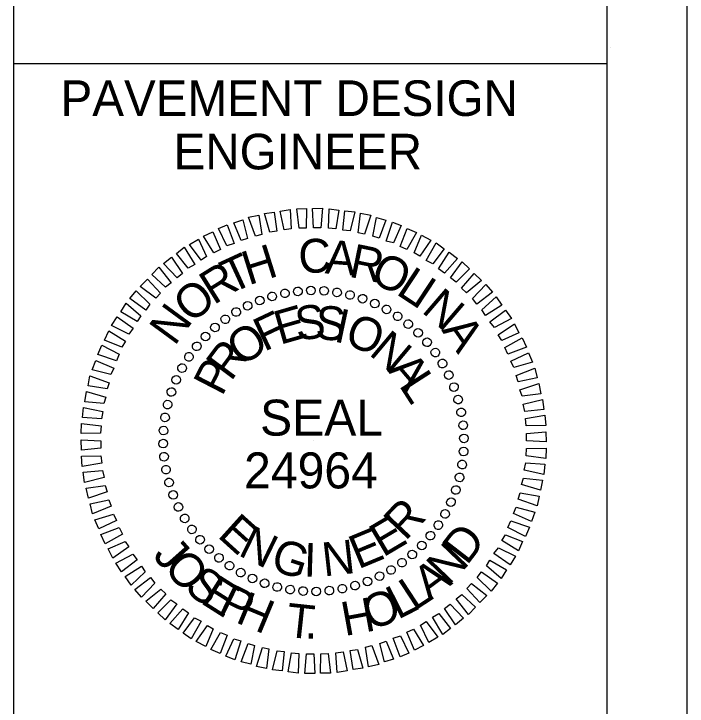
# Model space of a CAD drawing. Extents: x 1553884 to 1554215, y 810431 to 810779.
# Drawn here: x 1554139.32 to 1554156.35, y 810553.55 to 810571.05 of the extents above; entities that cross this region are included whole.
import ezdxf

# ---------------------------------------------------------------- set-up
doc = ezdxf.new("R2010")
doc.units = 0
for name, color, linetype in [('Exist Structure Minor Drop Inlet Top Elevation', 7, 'Continuous'), ('Old_Level_2', 7, 'Continuous'), ('Prop Lane Arrow CELL', 7, 'Continuous'), ('Typical Arrow Superelevation CELL', 7, 'Continuous')]:
    doc.layers.add(name, color=color, linetype=linetype)

msp = doc.modelspace()

# ---------------------------------------------------------------- linework, layer by layer
at = {"layer": 'Exist Structure Minor Drop Inlet Top Elevation'}
for p, q in [((1554154.423, 810570.205), (1554154.423, 810570.205)), ((1554146.178, 810563.991), (1554146.178, 810563.991)), ((1554146.503, 810564.042), (1554146.503, 810564.042)), ((1554146.837, 810564.063), (1554146.837, 810564.063)), ((1554147.171, 810564.054), (1554147.171, 810564.054)), ((1554147.497, 810564.014), (1554147.497, 810564.014)), ((1554145.537, 810563.813), (1554145.537, 810563.813)), ((1554145.853, 810563.917), (1554145.853, 810563.917)), ((1554147.824, 810563.952), (1554147.824, 810563.952)), ((1554148.144, 810563.859), (1554148.144, 810563.859)), ((1554145.236, 810563.679), (1554145.236, 810563.679)), ((1554148.45, 810563.735), (1554148.45, 810563.735)), ((1554144.943, 810563.522), (1554144.943, 810563.522)), ((1554148.748, 810563.589), (1554148.748, 810563.589)), ((1554144.665, 810563.335), (1554144.665, 810563.335)), ((1554149.032, 810563.411), (1554149.032, 810563.411)), ((1554144.403, 810563.134), (1554144.403, 810563.134)), ((1554149.301, 810563.219), (1554149.301, 810563.219)), ((1554149.547, 810562.996), (1554149.547, 810562.996)), ((1554144.165, 810562.902), (1554144.165, 810562.902)), ((1554149.779, 810562.757), (1554149.779, 810562.757)), ((1554143.942, 810562.655), (1554143.942, 810562.655)), ((1554149.981, 810562.495), (1554149.981, 810562.495)), ((1554143.749, 810562.386), (1554143.749, 810562.386)), ((1554150.168, 810562.218), (1554150.168, 810562.218)), ((1554143.572, 810562.103), (1554143.572, 810562.103)), ((1554150.324, 810561.925), (1554150.324, 810561.925)), ((1554143.426, 810561.805), (1554143.426, 810561.805)), ((1554150.459, 810561.624), (1554150.459, 810561.624)), ((1554143.302, 810561.499), (1554143.302, 810561.499)), ((1554143.209, 810561.179), (1554143.209, 810561.179)), ((1554150.563, 810561.307), (1554150.563, 810561.307)), ((1554143.146, 810560.852), (1554143.146, 810560.852)), ((1554150.637, 810560.982), (1554150.637, 810560.982)), ((1554150.688, 810560.657), (1554150.688, 810560.657)), ((1554143.107, 810560.525), (1554143.107, 810560.525)), ((1554150.709, 810560.324), (1554150.709, 810560.324)), ((1554143.097, 810560.191), (1554143.097, 810560.191)), ((1554146.903, 810560.258), (1554146.903, 810560.258)), ((1554150.699, 810559.99), (1554150.699, 810559.99)), ((1554143.118, 810559.858), (1554143.118, 810559.858)), ((1554150.66, 810559.663), (1554150.66, 810559.663)), ((1554143.17, 810559.533), (1554143.17, 810559.533)), ((1554150.597, 810559.336), (1554150.597, 810559.336)), ((1554143.243, 810559.208), (1554143.243, 810559.208)), ((1554143.348, 810558.891), (1554143.348, 810558.891)), ((1554150.504, 810559.016), (1554150.504, 810559.016)), ((1554143.482, 810558.59), (1554143.482, 810558.59)), ((1554150.38, 810558.711), (1554150.38, 810558.711)), ((1554150.234, 810558.412), (1554150.234, 810558.412)), ((1554143.639, 810558.297), (1554143.639, 810558.297)), ((1554143.825, 810558.02), (1554143.825, 810558.02)), ((1554150.057, 810558.129), (1554150.057, 810558.129)), ((1554149.865, 810557.86), (1554149.865, 810557.86)), ((1554144.027, 810557.758), (1554144.027, 810557.758)), ((1554144.259, 810557.519), (1554144.259, 810557.519)), ((1554149.641, 810557.613), (1554149.641, 810557.613)), ((1554149.403, 810557.382), (1554149.403, 810557.382)), ((1554144.505, 810557.296), (1554144.505, 810557.296)), ((1554149.141, 810557.18), (1554149.141, 810557.18)), ((1554144.774, 810557.104), (1554144.774, 810557.104)), ((1554148.864, 810556.993), (1554148.864, 810556.993)), ((1554145.058, 810556.927), (1554145.058, 810556.927)), ((1554148.571, 810556.836), (1554148.571, 810556.836)), ((1554145.356, 810556.78), (1554145.356, 810556.78)), ((1554145.662, 810556.656), (1554145.662, 810556.656)), ((1554148.269, 810556.702), (1554148.269, 810556.702)), ((1554145.982, 810556.563), (1554145.982, 810556.563)), ((1554146.309, 810556.501), (1554146.309, 810556.501)), ((1554146.636, 810556.461), (1554146.636, 810556.461)), ((1554146.969, 810556.452), (1554146.969, 810556.452)), ((1554147.303, 810556.473), (1554147.303, 810556.473)), ((1554147.628, 810556.524), (1554147.628, 810556.524)), ((1554147.953, 810556.598), (1554147.953, 810556.598))]:
    msp.add_line(p, q, dxfattribs=at)
for points in [[(1554146.158, 810565.591), (1554146.058, 810566.067), (1554146.308, 810566.109), (1554146.339, 810565.617)], [(1554146.536, 810565.635), (1554146.475, 810566.127), (1554146.725, 810566.132), (1554146.718, 810565.638)], [(1554146.9, 810565.642), (1554146.876, 810566.134), (1554147.126, 810566.138), (1554147.082, 810565.645)], [(1554147.279, 810565.633), (1554147.293, 810566.126), (1554147.544, 810566.093), (1554147.462, 810565.614)], [(1554147.644, 810565.587), (1554147.696, 810566.073), (1554147.947, 810566.047), (1554147.827, 810565.567)], [(1554145.432, 810565.434), (1554145.257, 810565.909), (1554145.514, 810565.966), (1554145.591, 810565.475)], [(1554145.795, 810565.531), (1554145.658, 810566.007), (1554145.907, 810566.042), (1554145.976, 810565.557)], [(1554148.032, 810565.517), (1554148.092, 810566.011), (1554148.351, 810565.963), (1554148.192, 810565.482)], [(1554148.398, 810565.433), (1554148.496, 810565.905), (1554148.732, 810565.841), (1554148.558, 810565.382)], [(1554144.709, 810565.186), (1554144.496, 810565.623), (1554144.715, 810565.717), (1554144.89, 810565.243)], [(1554145.07, 810565.322), (1554144.881, 810565.773), (1554145.114, 810565.846), (1554145.229, 810565.377)], [(1554148.741, 810565.31), (1554148.899, 810565.79), (1554149.121, 810565.703), (1554148.924, 810565.26)], [(1554144.378, 810565.014), (1554144.121, 810565.434), (1554144.354, 810565.544), (1554144.544, 810565.092)], [(1554149.092, 810565.172), (1554149.266, 810565.63), (1554149.503, 810565.528), (1554149.26, 810565.099)], [(1554149.444, 810565.011), (1554149.633, 810565.454), (1554149.871, 810565.329), (1554149.59, 810564.923)], [(1554144.055, 810564.826), (1554143.76, 810565.223), (1554143.993, 810565.356), (1554144.198, 810564.92)], [(1554149.751, 810564.819), (1554150.001, 810565.264), (1554150.201, 810565.115), (1554149.919, 810564.731)], [(1554143.733, 810564.623), (1554143.438, 810564.997), (1554143.633, 810565.152), (1554143.898, 810564.717)], [(1554150.065, 810564.605), (1554150.331, 810565.027), (1554150.538, 810564.871), (1554150.211, 810564.501)], [(1554143.449, 810564.383), (1554143.109, 810564.741), (1554143.311, 810564.904), (1554143.591, 810564.492)], [(1554150.365, 810564.375), (1554150.661, 810564.782), (1554150.846, 810564.603), (1554150.511, 810564.272)], [(1554143.157, 810564.143), (1554142.81, 810564.463), (1554142.989, 810564.648), (1554143.299, 810564.252)], [(1554150.643, 810564.122), (1554150.962, 810564.492), (1554151.147, 810564.313), (1554150.766, 810564.003)], [(1554142.912, 810563.866), (1554142.52, 810564.162), (1554142.699, 810564.348), (1554143.031, 810563.989)], [(1554150.92, 810563.854), (1554151.255, 810564.209), (1554151.425, 810564.014), (1554151.029, 810563.712)], [(1554142.659, 810563.566), (1554142.252, 810563.854), (1554142.416, 810564.054), (1554142.763, 810563.712)], [(1554151.16, 810563.57), (1554151.518, 810563.902), (1554151.666, 810563.685), (1554151.254, 810563.427)], [(1554142.444, 810563.274), (1554142.023, 810563.517), (1554142.163, 810563.739), (1554142.533, 810563.419)], [(1554151.363, 810563.263), (1554151.759, 810563.565), (1554151.907, 810563.348), (1554151.479, 810563.121)], [(1554142.23, 810562.959), (1554141.794, 810563.171), (1554141.934, 810563.394), (1554142.341, 810563.105)], [(1554151.573, 810562.94), (1554151.985, 810563.22), (1554152.095, 810562.987), (1554151.667, 810562.798)], [(1554142.054, 810562.63), (1554141.618, 810562.804), (1554141.72, 810563.041), (1554142.142, 810562.776)], [(1554151.738, 810562.617), (1554152.174, 810562.86), (1554152.284, 810562.626), (1554151.817, 810562.452)], [(1554141.916, 810562.279), (1554141.443, 810562.437), (1554141.545, 810562.674), (1554141.989, 810562.447)], [(1554151.888, 810562.271), (1554152.339, 810562.483), (1554152.435, 810562.25), (1554151.967, 810562.113)], [(1554141.778, 810561.935), (1554141.305, 810562.056), (1554141.392, 810562.292), (1554141.851, 810562.096)], [(1554152.023, 810561.909), (1554152.498, 810562.099), (1554152.555, 810561.85), (1554152.079, 810561.751)], [(1554141.678, 810561.569), (1554141.199, 810561.652), (1554141.247, 810561.903), (1554141.728, 810561.729)], [(1554152.121, 810561.547), (1554152.596, 810561.707), (1554152.653, 810561.45), (1554152.176, 810561.389)], [(1554141.593, 810561.204), (1554141.115, 810561.248), (1554141.163, 810561.507), (1554141.644, 810561.364)], [(1554152.203, 810561.184), (1554152.694, 810561.307), (1554152.728, 810561.049), (1554152.244, 810561.003)], [(1554141.539, 810560.816), (1554141.054, 810560.846), (1554141.079, 810561.104), (1554141.574, 810560.999)], [(1554152.262, 810560.821), (1554152.754, 810560.906), (1554152.773, 810560.648), (1554152.281, 810560.64)], [(1554141.515, 810560.452), (1554141.023, 810560.443), (1554141.033, 810560.701), (1554141.527, 810560.634)], [(1554152.284, 810560.442), (1554152.776, 810560.489), (1554152.781, 810560.231), (1554152.287, 810560.261)], [(1554141.522, 810560.073), (1554141.03, 810560.026), (1554141.025, 810560.284), (1554141.519, 810560.255)], [(1554152.291, 810560.063), (1554152.783, 810560.072), (1554152.773, 810559.814), (1554152.279, 810559.881)], [(1554141.544, 810559.694), (1554141.052, 810559.609), (1554141.033, 810559.867), (1554141.525, 810559.876)], [(1554152.267, 810559.699), (1554152.753, 810559.669), (1554152.727, 810559.411), (1554152.232, 810559.516)], [(1554141.603, 810559.331), (1554141.112, 810559.208), (1554141.078, 810559.466), (1554141.562, 810559.512)], [(1554152.213, 810559.311), (1554152.691, 810559.267), (1554152.643, 810559.008), (1554152.163, 810559.151)], [(1554141.685, 810558.968), (1554141.21, 810558.808), (1554141.153, 810559.065), (1554141.63, 810559.126)], [(1554152.128, 810558.946), (1554152.607, 810558.863), (1554152.559, 810558.612), (1554152.078, 810558.786)], [(1554141.783, 810558.606), (1554141.308, 810558.416), (1554141.251, 810558.665), (1554141.727, 810558.764)], [(1554152.028, 810558.58), (1554152.501, 810558.459), (1554152.414, 810558.223), (1554151.955, 810558.42)], [(1554141.918, 810558.244), (1554141.467, 810558.032), (1554141.372, 810558.265), (1554141.839, 810558.402)], [(1554151.89, 810558.236), (1554152.363, 810558.078), (1554152.261, 810557.841), (1554151.817, 810558.068)], [(1554142.068, 810557.898), (1554141.632, 810557.655), (1554141.522, 810557.889), (1554141.989, 810558.064)], [(1554151.752, 810557.885), (1554152.188, 810557.711), (1554152.086, 810557.474), (1554151.664, 810557.74)], [(1554142.233, 810557.575), (1554141.821, 810557.295), (1554141.711, 810557.528), (1554142.139, 810557.717)], [(1554151.576, 810557.556), (1554152.012, 810557.344), (1554151.872, 810557.121), (1554151.465, 810557.41)], [(1554142.443, 810557.253), (1554142.047, 810556.95), (1554141.899, 810557.167), (1554142.327, 810557.395)], [(1554151.362, 810557.241), (1554151.783, 810556.998), (1554151.643, 810556.776), (1554151.273, 810557.096)], [(1554142.646, 810556.945), (1554142.288, 810556.613), (1554142.14, 810556.83), (1554142.552, 810557.088)], [(1554142.886, 810556.661), (1554142.551, 810556.306), (1554142.38, 810556.501), (1554142.777, 810556.803)], [(1554151.147, 810556.949), (1554151.554, 810556.661), (1554151.39, 810556.461), (1554151.043, 810556.804)], [(1554150.894, 810556.649), (1554151.286, 810556.353), (1554151.107, 810556.168), (1554150.775, 810556.526)], [(1554143.164, 810556.393), (1554142.844, 810556.023), (1554142.659, 810556.202), (1554143.04, 810556.512)], [(1554150.649, 810556.372), (1554150.996, 810556.052), (1554150.817, 810555.867), (1554150.507, 810556.263)], [(1554143.441, 810556.14), (1554143.145, 810555.733), (1554142.96, 810555.912), (1554143.295, 810556.243)], [(1554150.357, 810556.132), (1554150.697, 810555.774), (1554150.495, 810555.611), (1554150.215, 810556.023)], [(1554143.741, 810555.91), (1554143.475, 810555.488), (1554143.268, 810555.644), (1554143.595, 810556.014)], [(1554144.056, 810555.696), (1554143.805, 810555.251), (1554143.606, 810555.4), (1554143.887, 810555.784)], [(1554150.073, 810555.892), (1554150.368, 810555.518), (1554150.173, 810555.363), (1554149.908, 810555.798)], [(1554144.362, 810555.504), (1554144.173, 810555.061), (1554143.935, 810555.186), (1554144.217, 810555.592)], [(1554149.751, 810555.689), (1554150.046, 810555.292), (1554149.813, 810555.159), (1554149.608, 810555.595)], [(1554144.714, 810555.343), (1554144.54, 810554.885), (1554144.303, 810554.987), (1554144.546, 810555.416)], [(1554149.428, 810555.501), (1554149.685, 810555.081), (1554149.452, 810554.971), (1554149.262, 810555.423)], [(1554145.065, 810555.205), (1554144.907, 810554.725), (1554144.685, 810554.812), (1554144.882, 810555.255)], [(1554149.097, 810555.329), (1554149.31, 810554.893), (1554149.091, 810554.798), (1554148.916, 810555.272)], [(1554145.408, 810555.082), (1554145.311, 810554.61), (1554145.074, 810554.675), (1554145.248, 810555.133)], [(1554148.374, 810555.081), (1554148.549, 810554.606), (1554148.292, 810554.549), (1554148.215, 810555.04)], [(1554148.736, 810555.193), (1554148.925, 810554.742), (1554148.692, 810554.669), (1554148.577, 810555.138)], [(1554145.774, 810554.998), (1554145.714, 810554.504), (1554145.456, 810554.552), (1554145.614, 810555.033)], [(1554146.162, 810554.929), (1554146.11, 810554.442), (1554145.859, 810554.468), (1554145.98, 810554.948)], [(1554146.527, 810554.882), (1554146.513, 810554.389), (1554146.262, 810554.422), (1554146.344, 810554.901)], [(1554146.906, 810554.873), (1554146.93, 810554.381), (1554146.68, 810554.377), (1554146.724, 810554.87)], [(1554147.27, 810554.88), (1554147.331, 810554.388), (1554147.081, 810554.384), (1554147.088, 810554.876)], [(1554147.648, 810554.924), (1554147.748, 810554.448), (1554147.498, 810554.406), (1554147.467, 810554.898)], [(1554148.011, 810554.983), (1554148.148, 810554.508), (1554147.899, 810554.474), (1554147.83, 810554.958)]]:
    msp.add_lwpolyline(points, close=True, dxfattribs=at)
for centre, major_axis in [((1554146.505, 810564.037), (-0.011, 0.109)), ((1554146.836, 810564.057), (-0.002, 0.109)), ((1554147.168, 810564.049), (0.008, 0.109)), ((1554145.854, 810563.91), (-0.03, 0.105)), ((1554146.177, 810563.988), (-0.021, 0.107)), ((1554147.497, 810564.011), (0.017, 0.108)), ((1554147.823, 810563.945), (0.026, 0.106)), ((1554148.141, 810563.851), (0.036, 0.103)), ((1554145.235, 810563.673), (-0.0479, 0.0981)), ((1554145.54, 810563.805), (-0.039, 0.102)), ((1554148.449, 810563.729), (0.0444, 0.0997)), ((1554144.944, 810563.515), (-0.0562, 0.0936)), ((1554148.746, 810563.581), (0.0529, 0.0955)), ((1554144.667, 810563.331), (-0.0642, 0.0883)), ((1554149.029, 810563.408), (0.0611, 0.0905)), ((1554149.296, 810563.21), (0.0687, 0.0849)), ((1554144.407, 810563.125), (-0.0716, 0.0824)), ((1554149.544, 810562.99), (0.0758, 0.0785)), ((1554144.167, 810562.897), (-0.0785, 0.0758)), ((1554143.947, 810562.648), (-0.0849, 0.0687)), ((1554149.773, 810562.75), (0.0824, 0.0716)), ((1554149.979, 810562.49), (0.0883, 0.0642)), ((1554143.749, 810562.381), (-0.0905, 0.0611)), ((1554143.576, 810562.098), (-0.0955, 0.0529)), ((1554150.163, 810562.213), (0.0936, 0.0562)), ((1554150.321, 810561.922), (0.0981, 0.0479)), ((1554143.428, 810561.801), (-0.0997, 0.0444)), ((1554150.453, 810561.618), (0.102, 0.039)), ((1554143.306, 810561.493), (-0.103, 0.036)), ((1554150.558, 810561.303), (0.105, 0.03)), ((1554143.212, 810561.175), (-0.106, 0.026)), ((1554150.636, 810560.98), (0.107, 0.021)), ((1554143.146, 810560.85), (-0.108, 0.017)), ((1554150.685, 810560.652), (0.109, 0.011)), ((1554143.108, 810560.52), (-0.109, 0.008)), ((1554143.1, 810560.188), (-0.109, -0.002)), ((1554150.705, 810560.321), (0.109, 0.002)), ((1554143.12, 810559.857), (-0.109, -0.011)), ((1554150.697, 810559.989), (0.109, -0.008)), ((1554150.659, 810559.66), (0.108, -0.017)), ((1554143.169, 810559.529), (-0.107, -0.021)), ((1554150.593, 810559.334), (0.106, -0.026)), ((1554143.247, 810559.206), (-0.105, -0.03)), ((1554150.499, 810559.016), (0.103, -0.036)), ((1554143.352, 810558.892), (-0.102, -0.039)), ((1554150.377, 810558.708), (0.0997, -0.0444)), ((1554143.484, 810558.587), (-0.0981, -0.0479)), ((1554143.642, 810558.296), (-0.0936, -0.0562)), ((1554150.229, 810558.411), (0.0955, -0.0529)), ((1554150.056, 810558.128), (0.0905, -0.0611)), ((1554143.826, 810558.019), (-0.0883, -0.0642)), ((1554144.032, 810557.759), (-0.0824, -0.0716)), ((1554149.858, 810557.861), (0.0849, -0.0687)), ((1554149.638, 810557.613), (0.0785, -0.0758)), ((1554144.261, 810557.519), (-0.0758, -0.0785)), ((1554149.398, 810557.384), (0.0716, -0.0824)), ((1554144.509, 810557.299), (-0.0687, -0.0849)), ((1554144.776, 810557.101), (-0.0611, -0.0905)), ((1554149.138, 810557.178), (0.0642, -0.0883)), ((1554145.059, 810556.928), (-0.0529, -0.0955)), ((1554148.861, 810556.994), (0.0562, -0.0936)), ((1554145.356, 810556.78), (-0.0444, -0.0997)), ((1554148.265, 810556.704), (0.039, -0.102)), ((1554148.57, 810556.836), (0.0479, -0.0981)), ((1554145.664, 810556.658), (-0.036, -0.103)), ((1554145.982, 810556.564), (-0.026, -0.106)), ((1554147.628, 810556.521), (0.021, -0.107)), ((1554147.951, 810556.599), (0.03, -0.105)), ((1554146.308, 810556.498), (-0.017, -0.108)), ((1554146.637, 810556.461), (-0.008, -0.109)), ((1554146.969, 810556.452), (0.002, -0.109)), ((1554147.3, 810556.472), (0.011, -0.109))]:
    msp.add_ellipse(centre, major_axis=major_axis, ratio=0.999708, dxfattribs=at)
at = {"layer": 'Old_Level_2'}
for p, q in [((1554139.321, 810434.329), (1554139.325, 810592.576)), ((1554154.321, 810434.329), (1554154.325, 810592.576)), ((1554154.325, 810569.788), (1554139.325, 810569.788))]:
    msp.add_line(p, q, dxfattribs=at)
at = {"layer": 'Prop Lane Arrow CELL'}
msp.add_line((1554156.35, 810430.954), (1554156.35, 810595.951), dxfattribs=at)

# ---------------------------------------------------------------- texts
at = {"layer": 'Exist Structure Minor Drop Inlet Top Elevation'}
for s, height, rotation, p in [('C', 0.855, 2.9171, (1554146.539, 810564.488)), ('H', 0.855, 17.4535, (1554145.257, 810564.188)), ('A', 0.855, 355.649, (1554147.177, 810564.493)), ('R', 0.855, 348.3808, (1554147.77, 810564.412)), ('T', 0.855, 24.7216, (1554144.817, 810563.969)), ('O', 0.855, 333.8445, (1554148.29, 810564.304)), ('R', 0.855, 31.9898, (1554144.375, 810563.682)), ('L', 0.855, 326.5763, (1554148.962, 810563.983)), ('I', 0.855, 326.5763, (1554149.348, 810563.728)), ('O', 0.855, 39.2579, (1554143.802, 810563.204)), ('N', 0.855, 319.3082, (1554149.609, 810563.528)), ('N', 0.855, 53.7943, (1554143.385, 810562.636)), ('E', 0.855, 15.9853, (1554146.053, 810562.682)), ('S', 0.855, 6.6414, (1554146.482, 810562.791)), ('S', 0.855, 357.2975, (1554146.935, 810562.824)), ('F', 0.855, 25.3292, (1554145.653, 810562.504)), ('I', 0.855, 347.9535, (1554147.387, 810562.777)), ('O', 0.855, 338.6096, (1554147.647, 810562.721)), ('A', 0.855, 304.7718, (1554150.128, 810563.054)), ('O', 0.855, 34.6731, (1554145.089, 810562.121)), ('N', 0.855, 319.9218, (1554148.277, 810562.453)), ('R', 0.855, 53.361, (1554144.811, 810561.743)), ('P', 0.855, 62.7049, (1554144.587, 810561.362)), ('A', 0.855, 310.5779, (1554148.757, 810562.035)), ('L', 0.855, 302.7465, (1554149.046, 810561.668)), ('SEAL', 0.9096, 0, (1554145.549, 810560.39)), ('24964', 0.9099, 0, (1554145.144, 810559.056)), ('R', 0.855, 46.7271, (1554149.224, 810557.709)), ('E', 0.855, 317.8985, (1554144.446, 810557.846)), ('E', 0.855, 30.5764, (1554148.659, 810557.303)), ('N', 0.855, 334.0491, (1554144.967, 810557.378)), ('E', 0.855, 22.5011, (1554148.031, 810557.005)), ('D', 0.857, 52.4666, (1554150.78, 810557.09)), ('J', 0.857, 311.6821, (1554142.811, 810557.342)), ('G', 0.855, 342.1244, (1554145.776, 810557.01)), ('I', 0.855, 358.2751, (1554146.644, 810556.827)), ('N', 0.855, 6.3504, (1554147.162, 810556.829)), ('N', 0.857, 46.1346, (1554150.303, 810556.574)), ('O', 0.857, 311.6821, (1554143.083, 810557.036)), ('A', 0.857, 36.5104, (1554149.83, 810556.201)), ('S', 0.857, 321.2064, (1554143.604, 810556.501)), ('E', 0.857, 327.6382, (1554144.012, 810556.176)), ('P', 0.857, 334.1252, (1554144.441, 810555.901)), ('L', 0.857, 33.2732, (1554149.444, 810555.943)), ('O', 0.857, 20.2113, (1554148.336, 810555.458)), ('L', 0.857, 26.7624, (1554149.031, 810555.731)), ('H', 0.857, 337.3863, (1554144.9, 810555.681)), ('H', 0.857, 10.3321, (1554147.687, 810555.321)), ('T', 0.857, 353.8166, (1554146.181, 810555.311)), ('.', 0.857, 0.4221, (1554146.671, 810555.259))]:
    msp.add_text(s, height=height, rotation=rotation, dxfattribs=at).set_placement(p)
at = {"layer": 'Typical Arrow Superelevation CELL'}
for s, p in [('PAVEMENT DESIGN', (1554140.502, 810568.471)), ('ENGINEER', (1554143.36, 810567.121))]:
    msp.add_text(s, height=0.9, dxfattribs=at).set_placement(p)

doc.saveas('drawing.dxf')
